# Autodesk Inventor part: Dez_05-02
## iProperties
Created: 2005-12
Part Number: Dez_05-02
Document SubType Name: Modeling
Designer: W. Holzwarth
Author: W. Holzwarth
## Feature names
1. Extrusion1
2. Trennen2
3. Trennen3
4. Spiegeln1 [Mirror]
5. Runde Anordnung1 [Circular Pattern]
